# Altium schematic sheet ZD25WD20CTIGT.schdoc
size 127 x 101 mm
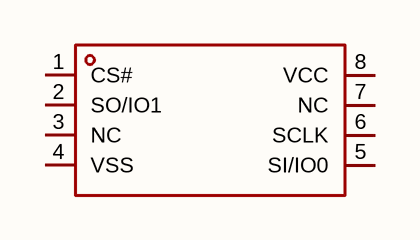
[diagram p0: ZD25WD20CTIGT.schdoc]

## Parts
U?  zd25wd20ctigt  [SOP-8_L4.9-W3.9-P1.27-LS6.0-BL]  (value not drawn)

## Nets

Not connected (* = marked no-connect by the designer): U? 1(CS#) 2(SO/IO1) 3(NC) 4(VSS) 5(SI/IO0) 6(SCLK) 7(NC) 8(VCC)

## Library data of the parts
U? = zd25wd20ctigt: 接口类型:SPI;存储容量:2Mbit;时钟频率(fc):104MHz;; Manufacturer: Zetta(澜智); AddInBom: yes; ModelId: 75c24a7891ee4dd6bdac16a7163ff87e; ModelName: SOP-8_L4.9-W3.9-P1.27-LS6.0-BL-1; ModelTransform: 192.913,236.22,0,0,0,0,-0.393,2.749,0; Interface: SPI; Memory Size: 2Mbit; Clock Frequency: 104MHz; Voltage - Supply: 1.65V~3.6V; Standby Supply Current: 0.5uA; Program / Erase Cycles: 100000次; Page Programming Time (Tpp): 2ms; Block Erase Time(tBE): 13ms; Data Retention - TDR (Year): 20年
